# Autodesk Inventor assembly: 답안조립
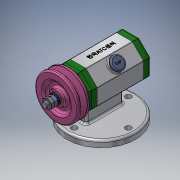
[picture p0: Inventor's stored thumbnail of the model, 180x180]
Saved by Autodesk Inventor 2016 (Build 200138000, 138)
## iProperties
Created: 2021-02
Part Number: 답안조립
Material: 일반
Document SubType Name: Assembly
Designer: Windows7
Author: Windows7
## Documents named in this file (14)
- C:\Users\Windows7\Desktop\710204V1008\답안조립.iam
- C:\Users\Windows7\Desktop\710204V1008\본체.ipt
- C:\Users\Windows7\Desktop\710204V1008\V벨트풀리.ipt
- C:\Users\Windows7\Desktop\710204V1008\고무캡.ipt
- C:\Users\Windows7\Desktop\710204V1008\너트 M8.ipt
- C:\Users\Windows7\Desktop\710204V1008\뒤커버.ipt
- C:\Users\Windows7\Desktop\710204V1008\베어링 15 x 32 x 9.ipt
- C:\Users\Windows7\Desktop\710204V1008\볼트 M4 x 12.ipt
- C:\Users\Windows7\Desktop\710204V1008\스프링와셔 8.ipt
- C:\Users\Windows7\Desktop\710204V1008\앞커버.ipt
- C:\Users\Windows7\Desktop\710204V1008\오일 실 15 25 7.ipt
- C:\Users\Windows7\Desktop\710204V1008\와셔 8x17.ipt
- C:\Users\Windows7\Desktop\710204V1008\축.ipt
- C:\Users\Windows7\Desktop\710204V1008\키 3 x 3 x 12.ipt
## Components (2 placed, 2 different names)
1. V벨트풀리:1
2. 고무캡:1 — 각도:4
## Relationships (1: Angle 1)
- 각도:4 [Angle]: 고무캡:1
